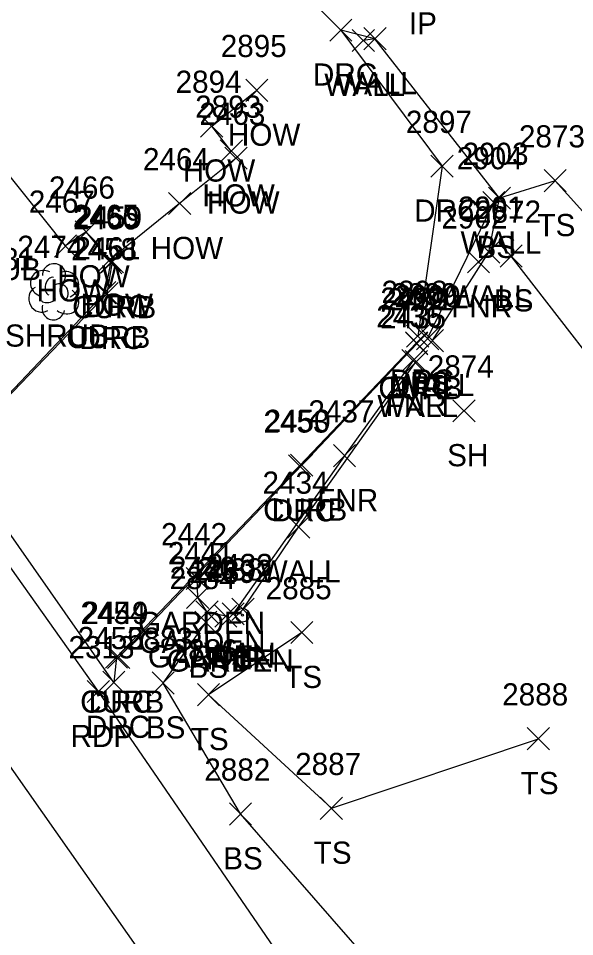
# Model space of a CAD drawing. Extents: x 1638344 to 1639591, y 610835 to 612202.
# Drawn here: x 1639007.1 to 1639057.3, y 611458.3 to 611541.1 of the extents above; entities that cross this region are included whole.
import ezdxf

# ---------------------------------------------------------------- set-up
doc = ezdxf.new("R2010")
doc.units = 0
for name, color, linetype in [('L_A', 7, 'Continuous'), ('L_I', 7, 'Continuous'), ('L_TIC', 7, 'Continuous'), ('LAPB', 7, 'Continuous'), ('LBC', 7, 'Continuous'), ('LELB', 7, 'Continuous'), ('LFNC', 7, 'Continuous'), ('LSH', 7, 'Continuous'), ('LSOGP', 7, 'Continuous'), ('LW', 7, 'Continuous'), ('M_A', 7, 'Continuous'), ('M_I', 7, 'Continuous'), ('MPIR', 7, 'Continuous'), ('P_A', 7, 'Continuous'), ('P_I', 7, 'Continuous'), ('P_TIC', 7, 'Continuous'), ('PET', 7, 'Continuous'), ('PRC', 7, 'Continuous'), ('R_A', 7, 'Continuous'), ('R_I', 7, 'Continuous'), ('R_TIC', 7, 'Continuous'), ('RC', 7, 'Continuous'), ('RDP', 7, 'Continuous')]:
    doc.layers.add(name, color=color, linetype=linetype)

msp = doc.modelspace()

# ---------------------------------------------------------------- linework, layer by layer
at = {"layer": 'L_TIC'}
for points in [[(1639038.271, 611538.22), (1639040.271, 611540.22)], [(1639040.271, 611538.22), (1639038.271, 611540.22)], [(1639037.218, 611538.059), (1639039.218, 611540.059)], [(1639039.218, 611538.059), (1639037.218, 611540.059)], [(1639027.625, 611533.568), (1639029.625, 611535.568)], [(1639029.625, 611533.568), (1639027.625, 611535.568)], [(1639023.557, 611530.339), (1639025.557, 611532.339)], [(1639025.557, 611530.339), (1639023.557, 611532.339)], [(1639025.322, 611528.095), (1639027.322, 611530.095)], [(1639027.322, 611528.095), (1639025.322, 611530.095)], [(1639025.748, 611527.452), (1639027.748, 611529.452)], [(1639027.748, 611527.452), (1639025.748, 611529.452)], [(1639054.505, 611525.418), (1639056.505, 611527.418)], [(1639056.505, 611525.418), (1639054.505, 611527.418)], [(1639020.663, 611523.358), (1639022.663, 611525.358)], [(1639022.663, 611523.358), (1639020.663, 611525.358)], [(1639048.977, 611523.449), (1639050.977, 611525.449)], [(1639050.977, 611523.449), (1639048.977, 611525.449)], [(1639049.498, 611523.843), (1639051.498, 611525.843)], [(1639051.498, 611523.843), (1639049.498, 611525.843)], [(1639012.241, 611520.802), (1639014.241, 611522.802)], [(1639014.241, 611520.802), (1639012.241, 611522.802)], [(1639010.378, 611519.532), (1639012.378, 611521.532)], [(1639012.378, 611519.532), (1639010.378, 611521.532)], [(1639048.527, 611518.991), (1639050.527, 611520.991)], [(1639050.527, 611518.991), (1639048.527, 611520.991)], [(1639050.548, 611518.63), (1639052.548, 611520.63)], [(1639052.548, 611518.63), (1639050.548, 611520.63)], [(1639014.341, 611518.249), (1639016.341, 611520.249)], [(1639016.341, 611518.249), (1639014.341, 611520.249)], [(1639047.602, 611518.105), (1639049.602, 611520.105)], [(1639049.602, 611518.105), (1639047.602, 611520.105)], [(1639043.019, 611511.183), (1639045.019, 611513.183)], [(1639045.019, 611511.183), (1639043.019, 611513.183)], [(1639043.461, 611511.002), (1639045.461, 611513.002)], [(1639045.461, 611511.002), (1639043.461, 611513.002)], [(1639041.7, 611509.204), (1639043.7, 611511.204)], [(1639043.7, 611509.204), (1639041.7, 611511.204)], [(1639041.992, 611509.106), (1639043.992, 611511.106)], [(1639043.992, 611509.106), (1639041.992, 611511.106)], [(1639046.286, 611504.673), (1639048.286, 611506.673)], [(1639048.286, 611504.673), (1639046.286, 611506.673)], [(1639035.528, 611500.622), (1639037.528, 611502.622)], [(1639037.528, 611500.622), (1639035.528, 611502.622)], [(1639031.391, 611494.198), (1639033.391, 611496.198)], [(1639033.391, 611494.198), (1639031.391, 611496.198)], [(1639022.248, 611489.552), (1639024.248, 611491.552)], [(1639024.248, 611489.552), (1639022.248, 611491.552)], [(1639022.294, 611487.843), (1639024.294, 611489.843)], [(1639024.294, 611487.843), (1639022.294, 611489.843)], [(1639023.133, 611486.53), (1639025.133, 611488.53)], [(1639025.133, 611486.53), (1639023.133, 611488.53)], [(1639024.823, 611486.156), (1639026.823, 611488.156)], [(1639026.823, 611486.156), (1639024.823, 611488.156)], [(1639025.486, 611486.376), (1639027.486, 611488.376)], [(1639027.486, 611486.376), (1639025.486, 611488.376)], [(1639026.368, 611486.776), (1639028.368, 611488.776)], [(1639028.368, 611486.776), (1639026.368, 611488.776)], [(1639023.022, 611485.602), (1639025.022, 611487.602)], [(1639025.022, 611485.602), (1639023.022, 611487.602)], [(1639031.677, 611484.683), (1639033.677, 611486.683)], [(1639033.677, 611484.683), (1639031.677, 611486.683)], [(1639019.173, 611480.133), (1639021.173, 611482.133)], [(1639021.173, 611480.133), (1639019.173, 611482.133)], [(1639023.258, 611479.079), (1639025.258, 611481.079)], [(1639025.258, 611479.079), (1639023.258, 611481.079)], [(1639052.996, 611475.11), (1639054.996, 611477.11)], [(1639054.996, 611475.11), (1639052.996, 611477.11)], [(1639034.337, 611468.837), (1639036.337, 611470.837)], [(1639036.337, 611468.837), (1639034.337, 611470.837)], [(1639026.148, 611468.331), (1639028.148, 611470.331)], [(1639028.148, 611468.331), (1639026.148, 611470.331)]]:
    msp.add_lwpolyline(points, dxfattribs=at)
at = {"layer": 'LAPB'}
msp.add_lwpolyline([(1639025.823, 611487.156), (1639024.133, 611487.53), (1639023.294, 611488.843), (1639023.248, 611490.552)], dxfattribs=at)
at = {"layer": 'LBC'}
for points in [[(1639026.748, 611528.452), (1639021.663, 611524.358), (1639015.341, 611519.249), (1639013.241, 611521.802), (1639011.378, 611520.532), (1638993.589, 611542.858), (1639005.17, 611552.615)], [(1639026.322, 611529.095), (1639024.557, 611531.339), (1639028.625, 611534.568)]]:
    msp.add_lwpolyline(points, dxfattribs=at)
at = {"layer": 'LELB'}
for points in [[(1639184.507, 611390.618), (1639168.398, 611364.735), (1639149.107, 611336.389), (1639141.991, 611332.951), (1639134.34, 611331.832), (1639128.543, 611335.119), (1639121.61, 611339.722), (1639110.957, 611351.756), (1639096.787, 611371.215), (1639095.544, 611383.482), (1639101.797, 611394.135), (1639116.538, 611418.413), (1639131.915, 611444.985), (1639113.359, 611469.053), (1639093.119, 611490.673), (1639071.049, 611509.19), (1639055.505, 611526.418)], [(1639044.019, 611512.183), (1639049.977, 611524.449)], [(1639085.934, 611391.346), (1639090.698, 611396.061), (1639108.287, 611427.176), (1639120.564, 611441.887), (1639103.979, 611463.141), (1639086.833, 611480.831), (1639063.48, 611504.24), (1639051.548, 611519.63)], [(1639083.1, 611392.426), (1639064.294, 611424.191), (1639047.175, 611446.369), (1639027.148, 611469.331), (1639020.173, 611481.133), (1639024.022, 611486.602)], [(1639032.677, 611485.683), (1639024.258, 611480.079), (1639035.337, 611469.837), (1639053.996, 611476.11)]]:
    msp.add_lwpolyline(points, dxfattribs=at)
at = {"layer": 'LFNC'}
msp.add_lwpolyline([(1639042.7, 611510.204), (1639036.528, 611501.622), (1639026.486, 611487.376)], dxfattribs=at)
at = {"layer": 'LSH'}
msp.add_line((1639010.295, 611516.457), (1639010.295, 611516.457), dxfattribs=at)
msp.add_line((1639010.295, 611516.457), (1639010.295, 611516.457), dxfattribs=at)
msp.add_arc((1639010.342, 611517.891), 1.047, 335.52715, 180.95627, dxfattribs=at)
for centre, major_axis, ratio, start_param, end_param in [((1639009.503, 611517.124), (1.21, -0.512), 0.895232, 1.570796, 4.712389), ((1639011.337, 611517.041), (-1.141, -0.483), 0.949671, 1.570796, 4.712389), ((1639010.087, 611516.915), (-0.208, -0.792), 0.645439, 3.141593, 6.283185), ((1639010.795, 611516.29), (-0.5, 0.667), 0.989748, 3.141593, 6.283185), ((1639009.212, 611515.748), (0.584, -1.042), 0.959034, 3.141593, 6.283185), ((1639011.295, 611515.624), (-1.09, 0.792), 0.841452, 1.570796, 4.712389), ((1639009.837, 611515.707), (-0.625, -0.083), 0.423636, 0, 3.141593), ((1639010.295, 611514.957), (0.265, 1.061), 0.942809, 1.570796, 4.712389)]:
    msp.add_ellipse(centre, major_axis=major_axis, ratio=ratio, start_param=start_param, end_param=end_param, dxfattribs=at)
at = {"layer": 'LSOGP'}
msp.add_lwpolyline([(1639180.862, 611428.141), (1639147.476, 611423.38), (1639131.915, 611444.985), (1639113.359, 611469.053), (1639093.119, 611490.673), (1639071.049, 611509.19), (1639055.505, 611526.418), (1639050.498, 611524.843), (1639039.271, 611539.22), (1639036.19, 611539.994), (1638995.826, 611580.211), (1638989.796, 611583.826), (1638969.061, 611612.068), (1638963.825, 611621.477), (1638962.785, 611633.117), (1638921.164, 611669.233), (1638917.309, 611673.068), (1638913.454, 611676.903), (1638906.896, 611682.615), (1638905.62, 611683.416), (1638890.128, 611696.929), (1638875.948, 611708.59)], dxfattribs=at)
at = {"layer": 'LW'}
for points in [[(1639044.461, 611512.002), (1639049.527, 611519.991), (1639050.498, 611524.843), (1639039.271, 611539.22), (1639038.218, 611539.059)], [(1639027.368, 611487.776), (1639032.391, 611495.198), (1639042.992, 611510.106)]]:
    msp.add_lwpolyline(points, dxfattribs=at)
at = {"layer": 'MPIR'}
for radius in [0.625, 0.0833]:
    msp.add_circle((1639027.332, 611487.242), radius, dxfattribs=at)
at = {"layer": 'P_TIC'}
for points in [[(1639013.337, 611479.362), (1639015.337, 611481.362)], [(1639015.337, 611479.362), (1639013.337, 611481.362)]]:
    msp.add_lwpolyline(points, dxfattribs=at)
at = {"layer": 'PET'}
msp.add_lwpolyline([(1639148.644, 611331.084), (1639142.07, 611329.181), (1639135.695, 611328.741), (1639125.685, 611331.146), (1639119.176, 611334.876), (1639114.186, 611340.569), (1639098.763, 611361.782), (1639080.318, 611387.337), (1639061.62, 611413.479), (1639039.15, 611444.22), (1639014.337, 611480.362), (1638988.412, 611516.904), (1638963.389, 611551.848), (1638935.462, 611588.701), (1638918.51, 611609.364), (1638899.727, 611630.857), (1638874.406, 611653.859), (1638846.552, 611674.469), (1638833.143, 611682.537), (1638823.865, 611689.161)], dxfattribs=at)
at = {"layer": 'PRC'}
msp.add_lwpolyline([(1638818.793, 611678.836), (1638843.976, 611663.347), (1638876.437, 611637.386), (1638906.243, 611607.195), (1638934.14, 611573.691), (1638965.308, 611531.428), (1638998.822, 611484.341), (1639033.825, 611434.483), (1639068.011, 611386.3), (1639093.943, 611350.49), (1639111.892, 611325.375), (1639129.228, 611302.77)], dxfattribs=at)
at = {"layer": 'R_TIC'}
for points in [[(1639035.19, 611538.994), (1639037.19, 611540.994)], [(1639037.19, 611538.994), (1639035.19, 611540.994)], [(1639044.314, 611526.727), (1639046.314, 611528.727)], [(1639046.314, 611526.727), (1639044.314, 611528.727)], [(1639014.446, 611518.023), (1639016.446, 611520.023)], [(1639016.446, 611518.023), (1639014.446, 611520.023)], [(1639014.6, 611518.115), (1639016.6, 611520.115)], [(1639016.6, 611518.115), (1639014.6, 611520.115)], [(1639013.918, 611515.323), (1639015.918, 611517.323)], [(1639015.918, 611515.323), (1639013.918, 611517.323)], [(1639014.137, 611515.241), (1639016.137, 611517.241)], [(1639016.137, 611515.241), (1639014.137, 611517.241)], [(1639042.123, 611511.402), (1639044.123, 611513.402)], [(1639044.123, 611511.402), (1639042.123, 611513.402)], [(1639042.011, 611510.789), (1639044.011, 611512.789)], [(1639044.011, 611510.789), (1639042.011, 611512.789)], [(1639042.047, 611510.723), (1639044.047, 611512.723)], [(1639044.047, 611510.723), (1639042.047, 611512.723)], [(1639031.473, 611499.709), (1639033.473, 611501.709)], [(1639033.473, 611499.709), (1639031.473, 611501.709)], [(1639031.664, 611499.772), (1639033.664, 611501.772)], [(1639033.664, 611499.772), (1639031.664, 611501.772)], [(1639014.977, 611482.459), (1639016.977, 611484.459)], [(1639016.977, 611482.459), (1639014.977, 611484.459)], [(1639015.171, 611482.456), (1639017.171, 611484.456)], [(1639017.171, 611482.456), (1639015.171, 611484.456)], [(1639014.731, 611480.189), (1639016.731, 611482.189)], [(1639016.731, 611480.189), (1639014.731, 611482.189)]]:
    msp.add_lwpolyline(points, dxfattribs=at)
at = {"layer": 'RC'}
for points in [[(1639015.446, 611519.023), (1639014.918, 611516.323), (1639002.408, 611503.14)], [(1639016.171, 611483.456), (1639032.664, 611500.772), (1639043.047, 611511.723)]]:
    msp.add_lwpolyline(points, dxfattribs=at)
at = {"layer": 'RDP'}
for points in [[(1639036.19, 611539.994), (1639045.314, 611527.727), (1639043.123, 611512.402)], [(1639043.011, 611511.789), (1639032.473, 611500.709), (1639015.977, 611483.459), (1639015.731, 611481.189), (1638999.895, 611503.8), (1639002.398, 611503.006), (1639015.137, 611516.241), (1639015.6, 611519.115)]]:
    msp.add_lwpolyline(points, dxfattribs=at)

# ---------------------------------------------------------------- texts
at = {"layer": 'L_A'}
for s, p in [('WALL', (1639034.706, 611534.059)), ('WALL', (1639035.759, 611534.22)), ('HOW', (1639026.011, 611529.568)), ('HOW', (1639021.943, 611526.339)), ('HOW', (1639023.708, 611524.095)), ('HOW', (1639024.134, 611523.452)), ('TS', (1639053.914, 611521.418)), ('HOW', (1639019.049, 611519.358)), ('WALL', (1639046.986, 611519.843)), ('BS', (1639048.418, 611519.449)), ('SHRUB', (1638999.806, 611517.451)), ('HOW', (1639010.627, 611516.802)), ('HOW', (1639008.764, 611515.532)), ('WALL', (1639046.015, 611514.991)), ('HOW', (1639012.727, 611514.249)), ('BS', (1639049.989, 611514.63)), ('FNR', (1639046.137, 611514.105)), ('SHRUB', (1639005.925, 611511.457)), ('WALL', (1639040.949, 611507.002)), ('BS', (1639042.46, 611507.183)), ('WALL', (1639039.48, 611505.106)), ('FNR', (1639040.235, 611505.204)), ('SH', (1639045.774, 611500.673)), ('FNR', (1639034.063, 611496.622)), ('WALL', (1639028.879, 611490.198)), ('GARDEN', (1639017.917, 611485.552)), ('GARDEN', (1639017.963, 611483.843)), ('WALL', (1639023.856, 611482.776)), ('GARDEN', (1639018.802, 611482.53)), ('GARDEN', (1639020.492, 611482.156)), ('FNR', (1639024.021, 611482.376)), ('BS', (1639022.463, 611481.602)), ('TS', (1639031.086, 611480.683)), ('BS', (1639018.614, 611476.133)), ('TS', (1639022.667, 611475.079)), ('TS', (1639052.405, 611471.11)), ('TS', (1639033.746, 611464.837)), ('BS', (1639025.589, 611464.331))]:
    msp.add_text(s, height=2, dxfattribs=at).set_placement(p)
at = {"layer": 'L_I'}
for s, p in [('2895', (1639025.365, 611537.568)), ('2894', (1639021.297, 611534.339)), ('2893', (1639023.062, 611532.095)), ('2463', (1639023.441, 611531.452)), ('2873', (1639052.245, 611529.418)), ('2904', (1639046.638, 611527.449)), ('2903', (1639047.159, 611527.843)), ('2464', (1639018.356, 611527.358)), ('2466', (1639009.879, 611524.802)), ('2467', (1639008.071, 611523.532)), ('2901', (1639046.755, 611522.991)), ('2872', (1639048.288, 611522.63)), ('2465', (1639012.034, 611522.249)), ('2902', (1639045.263, 611522.105)), ('2474', (1639007.035, 611519.457)), ('2481', (1639002.687, 611518.348)), ('2899', (1639040.751, 611515.183)), ('2900', (1639041.036, 611515.002)), ('2436', (1639039.385, 611513.204)), ('2435', (1639039.732, 611513.106)), ('2874', (1639044.026, 611508.673)), ('2437', (1639033.268, 611504.622)), ('2434', (1639029.131, 611498.198)), ('2442', (1639019.988, 611493.552)), ('2441', (1639020.601, 611491.843)), ('2440', (1639020.787, 611490.53)), ('2439', (1639022.555, 611490.156)), ('2438', (1639023.226, 611490.376)), ('2433', (1639024.108, 611490.776)), ('2884', (1639020.762, 611489.602)), ('2885', (1639029.417, 611488.683)), ('2883', (1639016.913, 611484.133)), ('2886', (1639020.943, 611483.079)), ('2888', (1639050.736, 611479.11)), ('2887', (1639032.077, 611472.837)), ('2882', (1639023.888, 611472.331))]:
    msp.add_text(s, height=2, dxfattribs=at).set_placement(p)
at = {"layer": 'M_A'}
for p in [(1639042.327, 611539.6), (1639026.379, 611482.242)]:
    msp.add_text('IP', height=2, dxfattribs=at).set_placement(p)
at = {"layer": 'M_I'}
msp.add_text('2892', height=2, dxfattribs=at).set_placement((1639024.072, 611490.242))
at = {"layer": 'P_A'}
msp.add_text('RDP', height=2, dxfattribs=at).set_placement((1639011.825, 611475.362))
at = {"layer": 'P_I'}
msp.add_text('2313', height=2, dxfattribs=at).set_placement((1639011.644, 611483.362))
at = {"layer": 'R_A'}
for s, p in [('DRC', (1639033.678, 611534.994)), ('DRC', (1639042.802, 611522.727)), ('CURB', (1639011.974, 611514.023)), ('DRC', (1639013.088, 611514.115)), ('CURB', (1639011.446, 611511.323)), ('DRC', (1639012.625, 611511.241)), ('CURB', (1639039.575, 611506.723)), ('DRC', (1639040.499, 611506.789)), ('DRC', (1639040.611, 611507.402)), ('CURB', (1639029.192, 611495.772)), ('DRC', (1639029.961, 611495.709)), ('CURB', (1639012.699, 611478.456)), ('DRC', (1639013.465, 611478.459)), ('DRC', (1639013.219, 611476.189))]:
    msp.add_text(s, height=2, dxfattribs=at).set_placement(p)
at = {"layer": 'R_I'}
for s, p in [('2897', (1639042.054, 611530.727)), ('2460', (1639012.052, 611522.023)), ('2459', (1639012.332, 611522.115)), ('2458', (1639011.877, 611519.241)), ('2461', (1639012.178, 611519.323)), ('2898', (1639039.863, 611515.402)), ('2452', (1639039.751, 611514.789)), ('2451', (1639040.354, 611514.723)), ('2453', (1639029.213, 611503.709)), ('2450', (1639029.318, 611503.772)), ('2454', (1639012.717, 611486.459)), ('2449', (1639012.903, 611486.456)), ('2455', (1639012.471, 611484.189))]:
    msp.add_text(s, height=2, dxfattribs=at).set_placement(p)

doc.saveas('drawing.dxf')
